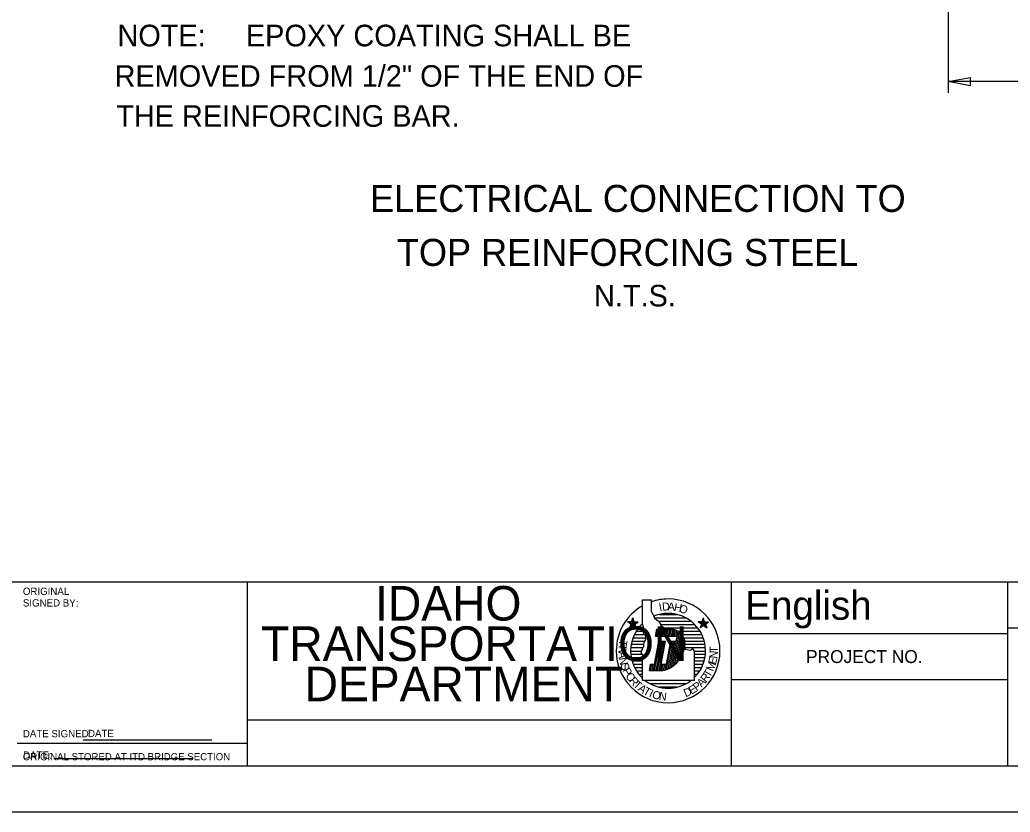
# Model space of a CAD drawing. Extents: x 0 to 2.83, y 0 to 1.96.
# Drawn here: x 0.961 to 1.856, y 0 to 0.716 of the extents above; entities that cross this region are included whole.
import ezdxf

# ---------------------------------------------------------------- set-up
doc = ezdxf.new("R2010")
doc.units = 0
for name, color, linetype in [('BORDER_ANNO_Cutsheet', 7, 'Continuous'), ('BRDG_ANNO_Anno-Large-Print', 7, 'Continuous'), ('BRDG_ANNO_Anno-Sheet', 7, 'Continuous'), ('BRDG_ANNO_Anno-Small-Print', 7, 'Continuous'), ('BRDG_ANNO_General-Notes', 7, 'Continuous')]:
    doc.layers.add(name, color=color, linetype=linetype)

msp = doc.modelspace()

# ---------------------------------------------------------------- linework, layer by layer
at = {"layer": 'BORDER_ANNO_Cutsheet'}
msp.add_lwpolyline([(0, 1.83333), (2.83333, 1.83333), (2.83333, 0), (0, 0)], close=True, dxfattribs=at)
at = {"layer": 'BRDG_ANNO_Anno-Large-Print'}
msp.add_line((0.99161, 0.04839), (1.11714, 0.04839), dxfattribs=at)
at = {"layer": 'BRDG_ANNO_Anno-Sheet'}
for p, q in [((0.125, 0.20833), (1.60417, 0.20833)), ((1.16667, 0.04167), (1.16667, 0.20833)), ((1.60417, 0.04167), (1.60417, 0.20833)), ((1.60417, 0.20833), (2.79167, 0.20833)), ((1.85417, 0.04167), (1.85417, 0.20833)), ((1.5237, 0.17021), (1.5237, 0.19193)), ((1.5237, 0.19193), (1.53193, 0.19193)), ((1.53193, 0.18109), (1.53193, 0.19193)), ((1.53193, 0.18109), (1.53411, 0.17719)), ((1.51677, 0.17), (1.51021, 0.17214)), ((1.5138, 0.17214), (1.51021, 0.17214)), ((1.51313, 0.17), (1.51021, 0.17214)), ((1.51609, 0.17214), (1.51198, 0.16651)), ((1.51313, 0.17), (1.51974, 0.17214)), ((1.5138, 0.17214), (1.51495, 0.17557)), ((1.5138, 0.17214), (1.51792, 0.16651)), ((1.51495, 0.16865), (1.51495, 0.17557)), ((1.51609, 0.17214), (1.51495, 0.17557)), ((1.51609, 0.17214), (1.51974, 0.17214)), ((1.51677, 0.17), (1.51974, 0.17214)), ((1.52453, 0.16719), (1.5237, 0.17021)), ((1.53411, 0.17719), (1.53453, 0.17542)), ((1.53453, 0.17542), (1.53885, 0.1724)), ((1.53474, 0.17568), (1.56255, 0.17568)), ((1.53875, 0.1787), (1.55484, 0.1787)), ((1.53875, 0.17271), (1.56724, 0.17271)), ((1.53885, 0.1724), (1.54021, 0.16891)), ((1.58062, 0.17), (1.57401, 0.17214)), ((1.57698, 0.17), (1.57401, 0.17214)), ((1.57766, 0.17214), (1.57401, 0.17214)), ((1.57995, 0.17214), (1.57583, 0.16651)), ((1.57698, 0.17), (1.58354, 0.17214)), ((1.57766, 0.17214), (1.5788, 0.17557)), ((1.57766, 0.17214), (1.58177, 0.16651)), ((1.5788, 0.16865), (1.5788, 0.17557)), ((1.57995, 0.17214), (1.5788, 0.17557)), ((1.57995, 0.17214), (1.58354, 0.17214)), ((1.58062, 0.17), (1.58354, 0.17214)), ((1.51313, 0.17), (1.51198, 0.16651)), ((1.51495, 0.16865), (1.51198, 0.16651)), ((1.51495, 0.16865), (1.51792, 0.16651)), ((1.51677, 0.17), (1.51792, 0.16651)), ((1.51807, 0.1637), (1.52438, 0.1637)), ((1.52016, 0.16672), (1.52448, 0.16672)), ((1.52286, 0.16969), (1.52385, 0.16969)), ((1.52453, 0.16458), (1.52453, 0.16719)), ((1.52453, 0.1624), (1.52453, 0.16458)), ((1.525, 0.16068), (1.52453, 0.1624)), ((1.53542, 0.15891), (1.53672, 0.16547)), ((1.53661, 0.15891), (1.53781, 0.16547)), ((1.53672, 0.16547), (1.55104, 0.16547)), ((1.53792, 0.15891), (1.53917, 0.16547)), ((1.53927, 0.15891), (1.54047, 0.16547)), ((1.5399, 0.16969), (1.57089, 0.16969)), ((1.54021, 0.16891), (1.54453, 0.16547)), ((1.54057, 0.15891), (1.54182, 0.16547)), ((1.54187, 0.15891), (1.54312, 0.16547)), ((1.54297, 0.16672), (1.57354, 0.16672)), ((1.54323, 0.15891), (1.54443, 0.16547)), ((1.54453, 0.15891), (1.54578, 0.16547)), ((1.54589, 0.15891), (1.54708, 0.16547)), ((1.54719, 0.15891), (1.54844, 0.16547)), ((1.54854, 0.15891), (1.54974, 0.16547)), ((1.54984, 0.15891), (1.55109, 0.16547)), ((1.54995, 0.1312), (1.55599, 0.16349)), ((1.55115, 0.15891), (1.55234, 0.1651)), ((1.55146, 0.13214), (1.55719, 0.16266)), ((1.5525, 0.15891), (1.55359, 0.16474)), ((1.55302, 0.13339), (1.55828, 0.16156)), ((1.5538, 0.15891), (1.55479, 0.16417)), ((1.55573, 0.1637), (1.57563, 0.1637)), ((1.57698, 0.17), (1.57583, 0.16651)), ((1.5788, 0.16865), (1.57583, 0.16651)), ((1.5788, 0.16865), (1.58177, 0.16651)), ((1.58062, 0.17), (1.58177, 0.16651)), ((1.60417, 0.16146), (1.85417, 0.16146)), ((1.85417, 0.16667), (2.52083, 0.16667)), ((1.51422, 0.15469), (1.52594, 0.15469)), ((1.5151, 0.15771), (1.52656, 0.15771)), ((1.51641, 0.16068), (1.52484, 0.16068)), ((1.52672, 0.15979), (1.525, 0.16068)), ((1.525, 0.1524), (1.52583, 0.15417)), ((1.525, 0.15026), (1.525, 0.1524)), ((1.52583, 0.15417), (1.52672, 0.1563)), ((1.52672, 0.1576), (1.52672, 0.15979)), ((1.52672, 0.1563), (1.52672, 0.1576)), ((1.53453, 0.13375), (1.53844, 0.15458)), ((1.53469, 0.12766), (1.53974, 0.15458)), ((1.5551, 0.15891), (1.53542, 0.15891)), ((1.53604, 0.12766), (1.54109, 0.15458)), ((1.53734, 0.12766), (1.5424, 0.15458)), ((1.53844, 0.15458), (1.54417, 0.15458)), ((1.5387, 0.12766), (1.54375, 0.15458)), ((1.54417, 0.15458), (1.54026, 0.13375)), ((1.54531, 0.13375), (1.54922, 0.15458)), ((1.54557, 0.12896), (1.55036, 0.15458)), ((1.54698, 0.12958), (1.55167, 0.15458)), ((1.54844, 0.13026), (1.55302, 0.15458)), ((1.54922, 0.15458), (1.55432, 0.15458)), ((1.55432, 0.15458), (1.5551, 0.15891)), ((1.55464, 0.1349), (1.55937, 0.16036)), ((1.5563, 0.13667), (1.56042, 0.15885)), ((1.55807, 0.13906), (1.56141, 0.15682)), ((1.55917, 0.16068), (1.57729, 0.16068)), ((1.56016, 0.14313), (1.56214, 0.15375)), ((1.56104, 0.15771), (1.57859, 0.15771)), ((1.56203, 0.15469), (1.57953, 0.15469)), ((1.51302, 0.14568), (1.52312, 0.14568)), ((1.51313, 0.1487), (1.52422, 0.1487)), ((1.51354, 0.15172), (1.52484, 0.15172)), ((1.5224, 0.14375), (1.52323, 0.14589)), ((1.5237, 0.14245), (1.5224, 0.14375)), ((1.52323, 0.14589), (1.5237, 0.14766)), ((1.5237, 0.14766), (1.525, 0.15026)), ((1.56172, 0.14813), (1.56234, 0.14719)), ((1.56187, 0.1487), (1.58062, 0.1487)), ((1.56229, 0.15172), (1.58021, 0.15172)), ((1.56234, 0.14719), (1.56495, 0.14677)), ((1.56495, 0.14677), (1.56755, 0.14635)), ((1.56755, 0.14635), (1.56885, 0.14807)), ((1.56885, 0.14807), (1.57057, 0.14547)), ((1.57042, 0.14568), (1.58073, 0.14568)), ((1.57057, 0.14547), (1.57057, 0.11896)), ((1.51318, 0.14271), (1.52344, 0.14271)), ((1.51359, 0.13969), (1.52484, 0.13969)), ((1.51427, 0.13672), (1.52365, 0.13672)), ((1.52453, 0.14115), (1.5237, 0.14245)), ((1.5237, 0.13766), (1.525, 0.13896)), ((1.5237, 0.11896), (1.5237, 0.13766)), ((1.525, 0.14026), (1.52453, 0.14115)), ((1.525, 0.13896), (1.525, 0.14026)), ((1.57057, 0.13969), (1.58016, 0.13969)), ((1.57057, 0.13672), (1.57948, 0.13672)), ((1.57062, 0.14271), (1.58057, 0.14271)), ((1.51531, 0.1337), (1.52354, 0.1337)), ((1.51661, 0.13068), (1.52354, 0.13068)), ((1.51833, 0.12771), (1.52359, 0.12771)), ((1.52995, 0.12766), (1.53109, 0.13375)), ((1.54104, 0.12766), (1.52995, 0.12766)), ((1.53073, 0.12766), (1.53187, 0.13375)), ((1.53109, 0.13375), (1.53453, 0.13375)), ((1.53208, 0.12766), (1.53323, 0.13375)), ((1.53339, 0.12766), (1.53453, 0.13375)), ((1.54, 0.12766), (1.54115, 0.13375)), ((1.54026, 0.13375), (1.54531, 0.13375)), ((1.54135, 0.12771), (1.5425, 0.13375)), ((1.54276, 0.12807), (1.5438, 0.13375)), ((1.54417, 0.12849), (1.5451, 0.13375)), ((1.57057, 0.1337), (1.57844, 0.1337)), ((1.57057, 0.13068), (1.57708, 0.13068)), ((1.57057, 0.12771), (1.57542, 0.12771)), ((1.52047, 0.12469), (1.52354, 0.12469)), ((1.52312, 0.12172), (1.52365, 0.12172)), ((1.57057, 0.11896), (1.5237, 0.11896)), ((1.57057, 0.12469), (1.57333, 0.12469)), ((1.60417, 0.11979), (1.85417, 0.11979)), ((1.56255, 0.11594), (1.53099, 0.11594)), ((1.5549, 0.11297), (1.53896, 0.11297)), ((1.16667, 0.08333), (1.60417, 0.08333))]:
    msp.add_line(p, q, dxfattribs=at)
msp.add_lwpolyline([(0.125, 1.79167), (2.79167, 1.79167), (2.79167, 0.04167), (0.125, 0.04167)], close=True, dxfattribs=at)
for centre, radius, start, end in [((1.54688, 0.14583), 0.04688, 90, 108.596), ((1.54688, 0.14583), 0.04688, 0, 90), ((1.54688, 0.14583), 0.04688, 119.63312, 180), ((1.54688, 0.14583), 0.03385, 90, 112.14518), ((1.54688, 0.14583), 0.03385, 0, 90), ((1.54688, 0.14583), 0.03385, 133.19257, 180), ((1.5486, 0.15201), 0.01368, 343.49805, 79.73615), ((1.54688, 0.14583), 0.04688, 180, 270), ((1.54688, 0.14583), 0.03385, 180.26444, 226.79463), ((1.53624, 0.15318), 0.02597, 280.64795, 348.77185), ((1.54688, 0.14583), 0.04688, 270, 0), ((1.54688, 0.14583), 0.03385, 314.427, 0), ((1.54688, 0.14583), 0.03385, 232.5658, 270), ((1.54688, 0.14583), 0.03385, 270, 307.45359)]:
    msp.add_arc(centre, radius, start, end, dxfattribs=at)
at = {"layer": 'BRDG_ANNO_Anno-Small-Print'}
for p, q in [((1.01802, 0.06552), (1.13447, 0.06552)), ((0.95833, 0.0625), (1.16667, 0.0625))]:
    msp.add_line(p, q, dxfattribs=at)
at = {"layer": 'BRDG_ANNO_General-Notes'}
for p, q in [((1.8001, 0.9426), (1.8001, 0.65031)), ((1.8001, 0.66031), (1.8201, 0.66406)), ((1.8201, 0.66406), (1.8201, 0.65656)), ((1.9201, 0.66031), (1.8001, 0.66031)), ((1.8201, 0.65656), (1.8001, 0.66031))]:
    msp.add_line(p, q, dxfattribs=at)

# ---------------------------------------------------------------- texts
at = {"layer": 'BRDG_ANNO_Anno-Large-Print'}
msp.add_text('DATE:', height=0.00656, dxfattribs=at).set_placement((0.96375, 0.04839))
at = {"layer": 'BRDG_ANNO_Anno-Sheet'}
for s, height, p in [('IDAHO', 0.03125, (1.28198, 0.17318)), ('English', 0.026042, (1.61672, 0.17391)), ('TRANSPORTATION', 0.03125, (1.17891, 0.13672)), ('PROJECT NO.', 0.0117188, (1.6716, 0.13479)), ('DEPARTMENT', 0.03125, (1.21828, 0.10026))]:
    msp.add_text(s, height=height, dxfattribs=at).set_placement(p)
for s, rotation, p in [('I', 11.95188, (1.53932, 0.18151)), ('D', 5.21184, (1.54177, 0.18203)), ('A', 357.8718, (1.54641, 0.18234)), ('H', 349.63177, (1.55182, 0.18198)), ('O', 342.19173, (1.5562, 0.18109)), ('T', 259.42648, (1.50318, 0.1563)), ('R', 266.0275, (1.50219, 0.15062)), ('A', 273.76404, (1.50193, 0.14505)), ('N', 83.19321, (1.59125, 0.13859)), ('T', 90.49256, (1.59182, 0.14411)), ('N', 280.37584, (1.5024, 0.13927)), ('S', 287.92792, (1.50359, 0.13365)), ('M', 67.71394, (1.58755, 0.12672)), ('E', 75.61046, (1.58995, 0.13307)), ('P', 295.49755, (1.50547, 0.12839)), ('O', 302.64464, (1.50797, 0.12333)), ('R', 52.33438, (1.58115, 0.11677)), ('T', 59.03624, (1.58448, 0.12125)), ('R', 309.90789, (1.51115, 0.11854)), ('T', 317.1211, (1.51479, 0.11427)), ('P', 37.66562, (1.57276, 0.10911)), ('A', 45, (1.57714, 0.11255)), ('A', 324.63754, (1.51901, 0.11047)), ('T', 331.75026, (1.5237, 0.10724)), ('I', 337.0213, (1.52911, 0.10448)), ('O', 343.32869, (1.53187, 0.10339)), ('N', 351.65981, (1.53823, 0.10167)), ('D', 22.98872, (1.56276, 0.1038)), ('E', 30.54757, (1.56797, 0.10615))]:
    msp.add_text(s, height=0.00724, rotation=rotation, dxfattribs=at).set_placement(p)
at = {"layer": 'BRDG_ANNO_Anno-Small-Print'}
for s, height, p in [('ORIGINAL', 0.006562, (0.96354, 0.19635)), ('SIGNED BY:', 0.006562, (0.96354, 0.18589)), ('DATE SIGNED:', 0.0065625, (0.96354, 0.06771)), ('DATE', 0.00656, (1.0224, 0.06797)), ('ORIGINAL STORED AT ITD BRIDGE SECTION', 0.0065181, (0.96354, 0.0469))]:
    msp.add_text(s, height=height, dxfattribs=at).set_placement(p)
at = {"layer": 'BRDG_ANNO_General-Notes'}
for s, height, p in [('NOTE:     EPOXY COATING SHALL BE', 0.0195312, (1.04906, 0.69219)), ('REMOVED FROM 1/2" OF THE END OF', 0.0195312, (1.04646, 0.65563)), ('THE REINFORCING BAR.', 0.0195312, (1.04792, 0.61948)), ('ELECTRICAL CONNECTION TO', 0.0244141, (1.2774, 0.54255)), ('TOP REINFORCING STEEL', 0.0244141, (1.30167, 0.49375)), ('N.T.S.', 0.019531, (1.4799, 0.45708))]:
    msp.add_text(s, height=height, dxfattribs=at).set_placement(p)

doc.saveas('drawing.dxf')
